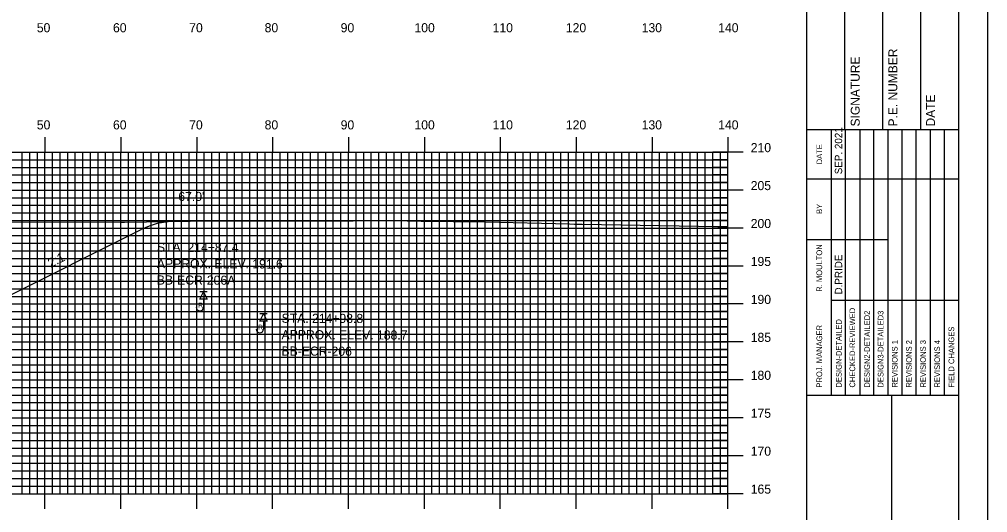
# Model space of a CAD drawing. Extents: x 1796027 to 1796370, y 442591 to 442811.
# Drawn here: x 1796239 to 1796366.6, y 442671.2 to 442736.2 of the extents above; entities that cross this region are included whole.
import ezdxf

# ---------------------------------------------------------------- set-up
doc = ezdxf.new("R2010")
doc.units = 0
for name, color, linetype in [('ANNOTATION', 7, 'Continuous'), ('BORDER', 7, 'Continuous'), ('BORING - REFUSAL', 7, 'Continuous'), ('D_Roadway_Centerline', 7, 'Continuous'), ('D_Text_Standard', 7, 'Continuous'), ('H_V ANNOTATION', 7, 'Continuous'), ('MAJOR', 7, 'Continuous'), ('MINOR', 7, 'Continuous'), ('PLOT BOUNDARY', 7, 'Continuous'), ('S_Roadway_Centerline', 7, 'Continuous')]:
    doc.layers.add(name, color=color, linetype=linetype)

msp = doc.modelspace()

# ---------------------------------------------------------------- linework, layer by layer
at = {"layer": 'ANNOTATION'}
msp.add_line((1796236.65, 442699.27), (1796255.09, 442708.49), dxfattribs=at)
msp.add_arc((1796259.56, 442699.54), 10, 90.854, 116.5651, dxfattribs=at)
at = {"layer": 'BORDER'}
for p, q in [((1796342.79, 442596.67), (1796342.79, 442806.67)), ((1796347.79, 442721.67), (1796347.79, 442738.97)), ((1796352.79, 442721.67), (1796352.79, 442738.97)), ((1796357.79, 442721.67), (1796357.79, 442738.97)), ((1796342.79, 442721.67), (1796362.79, 442721.67)), ((1796342.79, 442686.67), (1796362.79, 442686.67)), ((1796353.97, 442616.67), (1796353.97, 442686.67))]:
    msp.add_line(p, q, dxfattribs=at)
msp.add_lwpolyline([(1796042.79, 442596.67), (1796362.79, 442596.67), (1796362.79, 442806.67), (1796042.79, 442806.67)], close=True, dxfattribs=at)
for points in [[(1796346.02, 442715.17), (1796346.02, 442721.67)], [(1796347.89, 442686.68), (1796347.89, 442721.67)], [(1796349.75, 442721.67), (1796349.75, 442686.68)], [(1796351.61, 442686.68), (1796351.61, 442721.67)], [(1796353.48, 442686.68), (1796353.48, 442721.67)], [(1796355.34, 442686.68), (1796355.34, 442721.67)], [(1796357.2, 442686.68), (1796357.2, 442721.67)], [(1796359.07, 442686.68), (1796359.07, 442721.67)], [(1796360.93, 442686.68), (1796360.93, 442721.67)], [(1796346.02, 442686.68), (1796346.02, 442720.26)], [(1796342.79, 442715.17), (1796362.79, 442715.17)], [(1796342.79, 442707.17), (1796346.02, 442707.17)], [(1796346.02, 442707.17), (1796353.48, 442707.17)], [(1796346.02, 442699.17), (1796362.79, 442699.17)]]:
    msp.add_lwpolyline(points, dxfattribs=at)
at = {"layer": 'BORING - REFUSAL'}
for p, q in [((1796263.77, 442700.27), (1796262.81, 442700.27)), ((1796263.29, 442699.31), (1796263.29, 442698.25)), ((1796271.67, 442697.37), (1796270.71, 442697.37)), ((1796271.19, 442696.41), (1796271.19, 442695.35))]:
    msp.add_line(p, q, dxfattribs=at)
for points in [[(1796263.29, 442700.27), (1796263.77, 442699.31), (1796262.81, 442699.31)], [(1796271.19, 442697.37), (1796271.67, 442696.41), (1796270.71, 442696.41)]]:
    msp.add_lwpolyline(points, close=True, dxfattribs=at)
for centre in [(1796262.81, 442698.25), (1796270.71, 442695.35)]:
    msp.add_arc(centre, 0.485, 180, 0, dxfattribs=at)
at = {"layer": 'D_Roadway_Centerline'}
msp.add_lwpolyline([(1796155.7, 442693.47), (1796158.22, 442683.41), (1796162.22, 442684.41), (1796172.39, 442686.95), (1796180.39, 442687.27), (1796192.39, 442687.03), (1796204.39, 442686.79), (1796212.39, 442686.47), (1796222.57, 442683.93), (1796226.57, 442682.93), (1796230.65, 442699.27), (1796236.65, 442699.27), (1796255.09, 442708.49)], dxfattribs=at)
at = {"layer": 'MAJOR'}
for p, q in [((1796242.39, 442720.67), (1796242.39, 442718.67)), ((1796252.39, 442720.67), (1796252.39, 442718.67)), ((1796262.39, 442720.67), (1796262.39, 442718.67)), ((1796272.39, 442720.67), (1796272.39, 442718.67)), ((1796282.39, 442720.67), (1796282.39, 442718.67)), ((1796292.39, 442720.67), (1796292.39, 442718.67)), ((1796302.39, 442720.67), (1796302.39, 442718.67)), ((1796312.39, 442720.67), (1796312.39, 442718.67)), ((1796322.39, 442720.67), (1796322.39, 442718.67)), ((1796332.39, 442720.67), (1796332.39, 442718.67)), ((1796052.39, 442718.67), (1796332.39, 442718.67)), ((1796052.39, 442718.67), (1796332.39, 442718.67)), ((1796242.39, 442673.67), (1796242.39, 442718.67)), ((1796252.39, 442673.67), (1796252.39, 442718.67)), ((1796262.39, 442673.67), (1796262.39, 442718.67)), ((1796272.39, 442673.67), (1796272.39, 442718.67)), ((1796282.39, 442673.67), (1796282.39, 442718.67)), ((1796292.39, 442673.67), (1796292.39, 442718.67)), ((1796302.39, 442673.67), (1796302.39, 442718.67)), ((1796312.39, 442673.67), (1796312.39, 442718.67)), ((1796322.39, 442673.67), (1796322.39, 442718.67)), ((1796334.4, 442718.67), (1796330.39, 442718.67)), ((1796332.39, 442673.67), (1796332.39, 442718.67)), ((1796332.39, 442673.67), (1796332.39, 442718.67)), ((1796052.39, 442713.67), (1796332.39, 442713.67)), ((1796334.4, 442713.67), (1796330.39, 442713.67)), ((1796052.39, 442708.67), (1796332.39, 442708.67)), ((1796334.4, 442708.67), (1796330.39, 442708.67)), ((1796052.39, 442703.67), (1796332.39, 442703.67)), ((1796334.4, 442703.67), (1796330.39, 442703.67)), ((1796052.39, 442698.67), (1796332.39, 442698.67)), ((1796334.4, 442698.67), (1796330.39, 442698.67)), ((1796052.39, 442693.67), (1796332.39, 442693.67)), ((1796334.4, 442693.67), (1796330.39, 442693.67)), ((1796052.39, 442688.67), (1796332.39, 442688.67)), ((1796334.4, 442688.67), (1796330.39, 442688.67)), ((1796052.39, 442683.67), (1796332.39, 442683.67)), ((1796334.4, 442683.67), (1796330.39, 442683.67)), ((1796052.39, 442678.67), (1796332.39, 442678.67)), ((1796334.4, 442678.67), (1796330.39, 442678.67)), ((1796052.39, 442673.67), (1796332.39, 442673.67)), ((1796052.39, 442673.67), (1796332.39, 442673.67)), ((1796242.39, 442671.66), (1796242.39, 442673.67)), ((1796252.39, 442671.66), (1796252.39, 442673.67)), ((1796262.39, 442671.66), (1796262.39, 442673.67)), ((1796272.39, 442671.66), (1796272.39, 442673.67)), ((1796282.39, 442671.66), (1796282.39, 442673.67)), ((1796292.39, 442671.66), (1796292.39, 442673.67)), ((1796302.39, 442671.66), (1796302.39, 442673.67)), ((1796312.39, 442671.66), (1796312.39, 442673.67)), ((1796322.39, 442671.66), (1796322.39, 442673.67)), ((1796334.4, 442673.67), (1796330.39, 442673.67)), ((1796332.39, 442671.66), (1796332.39, 442673.67))]:
    msp.add_line(p, q, dxfattribs=at)
at = {"layer": 'MINOR'}
for p, q in [((1796239.39, 442673.67), (1796239.39, 442718.67)), ((1796240.39, 442673.67), (1796240.39, 442718.67)), ((1796241.39, 442673.67), (1796241.39, 442718.67)), ((1796243.39, 442673.67), (1796243.39, 442718.67)), ((1796244.39, 442673.67), (1796244.39, 442718.67)), ((1796245.39, 442673.67), (1796245.39, 442718.67)), ((1796246.39, 442673.67), (1796246.39, 442718.67)), ((1796247.39, 442673.67), (1796247.39, 442718.67)), ((1796248.39, 442673.67), (1796248.39, 442718.67)), ((1796249.39, 442673.67), (1796249.39, 442718.67)), ((1796250.39, 442673.67), (1796250.39, 442718.67)), ((1796251.39, 442673.67), (1796251.39, 442718.67)), ((1796253.39, 442673.67), (1796253.39, 442718.67)), ((1796254.39, 442673.67), (1796254.39, 442718.67)), ((1796255.39, 442673.67), (1796255.39, 442718.67)), ((1796256.39, 442673.67), (1796256.39, 442718.67)), ((1796257.39, 442673.67), (1796257.39, 442718.67)), ((1796258.39, 442673.67), (1796258.39, 442718.67)), ((1796259.39, 442673.67), (1796259.39, 442718.67)), ((1796260.39, 442673.67), (1796260.39, 442718.67)), ((1796261.39, 442673.67), (1796261.39, 442718.67)), ((1796263.39, 442673.67), (1796263.39, 442718.67)), ((1796264.39, 442673.67), (1796264.39, 442718.67)), ((1796265.39, 442673.67), (1796265.39, 442718.67)), ((1796266.39, 442673.67), (1796266.39, 442718.67)), ((1796267.39, 442673.67), (1796267.39, 442718.67)), ((1796268.39, 442673.67), (1796268.39, 442718.67)), ((1796269.39, 442673.67), (1796269.39, 442718.67)), ((1796270.39, 442673.67), (1796270.39, 442718.67)), ((1796271.39, 442673.67), (1796271.39, 442718.67)), ((1796273.39, 442673.67), (1796273.39, 442718.67)), ((1796274.39, 442673.67), (1796274.39, 442718.67)), ((1796275.39, 442673.67), (1796275.39, 442718.67)), ((1796276.39, 442673.67), (1796276.39, 442718.67)), ((1796277.39, 442673.67), (1796277.39, 442718.67)), ((1796278.39, 442673.67), (1796278.39, 442718.67)), ((1796279.39, 442673.67), (1796279.39, 442718.67)), ((1796280.39, 442673.67), (1796280.39, 442718.67)), ((1796281.39, 442673.67), (1796281.39, 442718.67)), ((1796283.39, 442673.67), (1796283.39, 442718.67)), ((1796284.39, 442673.67), (1796284.39, 442718.67)), ((1796285.39, 442673.67), (1796285.39, 442718.67)), ((1796286.39, 442673.67), (1796286.39, 442718.67)), ((1796287.39, 442673.67), (1796287.39, 442718.67)), ((1796288.39, 442673.67), (1796288.39, 442718.67)), ((1796289.39, 442673.67), (1796289.39, 442718.67)), ((1796290.39, 442673.67), (1796290.39, 442718.67)), ((1796291.39, 442673.67), (1796291.39, 442718.67)), ((1796293.39, 442673.67), (1796293.39, 442718.67)), ((1796294.39, 442673.67), (1796294.39, 442718.67)), ((1796295.39, 442673.67), (1796295.39, 442718.67)), ((1796296.39, 442673.67), (1796296.39, 442718.67)), ((1796297.39, 442673.67), (1796297.39, 442718.67)), ((1796298.39, 442673.67), (1796298.39, 442718.67)), ((1796299.39, 442673.67), (1796299.39, 442718.67)), ((1796300.39, 442673.67), (1796300.39, 442718.67)), ((1796301.39, 442673.67), (1796301.39, 442718.67)), ((1796303.39, 442673.67), (1796303.39, 442718.67)), ((1796304.39, 442673.67), (1796304.39, 442718.67)), ((1796305.39, 442673.67), (1796305.39, 442718.67)), ((1796306.39, 442673.67), (1796306.39, 442718.67)), ((1796307.39, 442673.67), (1796307.39, 442718.67)), ((1796308.39, 442673.67), (1796308.39, 442718.67)), ((1796309.39, 442673.67), (1796309.39, 442718.67)), ((1796310.39, 442673.67), (1796310.39, 442718.67)), ((1796311.39, 442673.67), (1796311.39, 442718.67)), ((1796313.39, 442673.67), (1796313.39, 442718.67)), ((1796314.39, 442673.67), (1796314.39, 442718.67)), ((1796315.39, 442673.67), (1796315.39, 442718.67)), ((1796316.39, 442673.67), (1796316.39, 442718.67)), ((1796317.39, 442673.67), (1796317.39, 442718.67)), ((1796318.39, 442673.67), (1796318.39, 442718.67)), ((1796319.39, 442673.67), (1796319.39, 442718.67)), ((1796320.39, 442673.67), (1796320.39, 442718.67)), ((1796321.39, 442673.67), (1796321.39, 442718.67)), ((1796323.39, 442673.67), (1796323.39, 442718.67)), ((1796324.39, 442673.67), (1796324.39, 442718.67)), ((1796325.39, 442673.67), (1796325.39, 442718.67)), ((1796326.39, 442673.67), (1796326.39, 442718.67)), ((1796327.39, 442673.67), (1796327.39, 442718.67)), ((1796328.39, 442673.67), (1796328.39, 442718.67)), ((1796329.39, 442673.67), (1796329.39, 442718.67)), ((1796330.39, 442673.67), (1796330.39, 442718.67)), ((1796331.39, 442673.67), (1796331.39, 442718.67)), ((1796052.39, 442717.67), (1796332.39, 442717.67)), ((1796332.39, 442717.67), (1796330.39, 442717.67)), ((1796052.39, 442716.67), (1796332.39, 442716.67)), ((1796052.39, 442715.67), (1796332.39, 442715.67)), ((1796332.39, 442716.67), (1796330.39, 442716.67)), ((1796332.39, 442715.67), (1796330.39, 442715.67)), ((1796052.39, 442714.67), (1796332.39, 442714.67)), ((1796332.39, 442714.67), (1796330.39, 442714.67)), ((1796052.39, 442712.67), (1796332.39, 442712.67)), ((1796332.39, 442712.67), (1796330.39, 442712.67)), ((1796052.39, 442711.67), (1796332.39, 442711.67)), ((1796052.39, 442710.67), (1796332.39, 442710.67)), ((1796332.39, 442711.67), (1796330.39, 442711.67)), ((1796332.39, 442710.67), (1796330.39, 442710.67)), ((1796052.39, 442709.67), (1796332.39, 442709.67)), ((1796332.39, 442709.67), (1796330.39, 442709.67)), ((1796052.39, 442707.67), (1796332.39, 442707.67)), ((1796332.39, 442707.67), (1796330.39, 442707.67)), ((1796052.39, 442706.67), (1796332.39, 442706.67)), ((1796052.39, 442705.67), (1796332.39, 442705.67)), ((1796332.39, 442706.67), (1796330.39, 442706.67)), ((1796332.39, 442705.67), (1796330.39, 442705.67)), ((1796052.39, 442704.67), (1796332.39, 442704.67)), ((1796332.39, 442704.67), (1796330.39, 442704.67)), ((1796052.39, 442702.67), (1796332.39, 442702.67)), ((1796052.39, 442701.67), (1796332.39, 442701.67)), ((1796332.39, 442702.67), (1796330.39, 442702.67)), ((1796332.39, 442701.67), (1796330.39, 442701.67)), ((1796052.39, 442700.67), (1796332.39, 442700.67)), ((1796332.39, 442700.67), (1796330.39, 442700.67)), ((1796052.39, 442699.67), (1796332.39, 442699.67)), ((1796332.39, 442699.67), (1796330.39, 442699.67)), ((1796052.39, 442697.67), (1796332.39, 442697.67)), ((1796052.39, 442696.67), (1796332.39, 442696.67)), ((1796332.39, 442697.67), (1796330.39, 442697.67)), ((1796332.39, 442696.67), (1796330.39, 442696.67)), ((1796052.39, 442695.67), (1796332.39, 442695.67)), ((1796332.39, 442695.67), (1796330.39, 442695.67)), ((1796052.39, 442694.67), (1796332.39, 442694.67)), ((1796332.39, 442694.67), (1796330.39, 442694.67)), ((1796052.39, 442692.67), (1796332.39, 442692.67)), ((1796332.39, 442692.67), (1796330.39, 442692.67)), ((1796052.39, 442691.67), (1796332.39, 442691.67)), ((1796332.39, 442691.67), (1796330.39, 442691.67)), ((1796052.39, 442690.67), (1796332.39, 442690.67)), ((1796332.39, 442690.67), (1796330.39, 442690.67)), ((1796052.39, 442689.67), (1796332.39, 442689.67)), ((1796332.39, 442689.67), (1796330.39, 442689.67)), ((1796052.39, 442687.67), (1796332.39, 442687.67)), ((1796332.39, 442687.67), (1796330.39, 442687.67)), ((1796052.39, 442686.67), (1796332.39, 442686.67)), ((1796332.39, 442686.67), (1796330.39, 442686.67)), ((1796052.39, 442685.67), (1796332.39, 442685.67)), ((1796332.39, 442685.67), (1796330.39, 442685.67)), ((1796052.39, 442684.67), (1796332.39, 442684.67)), ((1796332.39, 442684.67), (1796330.39, 442684.67)), ((1796052.39, 442682.67), (1796332.39, 442682.67)), ((1796332.39, 442682.67), (1796330.39, 442682.67)), ((1796052.39, 442681.67), (1796332.39, 442681.67)), ((1796332.39, 442681.67), (1796330.39, 442681.67)), ((1796052.39, 442680.67), (1796332.39, 442680.67)), ((1796332.39, 442680.67), (1796330.39, 442680.67)), ((1796052.39, 442679.67), (1796332.39, 442679.67)), ((1796332.39, 442679.67), (1796330.39, 442679.67)), ((1796052.39, 442677.67), (1796332.39, 442677.67)), ((1796332.39, 442677.67), (1796330.39, 442677.67)), ((1796052.39, 442676.67), (1796332.39, 442676.67)), ((1796332.39, 442676.67), (1796330.39, 442676.67)), ((1796052.39, 442675.67), (1796332.39, 442675.67)), ((1796332.39, 442675.67), (1796330.39, 442675.67)), ((1796052.39, 442674.67), (1796332.39, 442674.67)), ((1796332.39, 442674.67), (1796330.39, 442674.67))]:
    msp.add_line(p, q, dxfattribs=at)
at = {"layer": 'PLOT BOUNDARY'}
msp.add_lwpolyline([(1796026.61, 442590.55), (1796366.61, 442590.55), (1796366.61, 442810.55), (1796026.61, 442810.55)], close=True, dxfattribs=at)
at = {"layer": 'S_Roadway_Centerline'}
msp.add_lwpolyline([(1796237.54, 442709.5), (1796252.29, 442709.44), (1796252.72, 442709.44), (1796252.77, 442709.44), (1796252.86, 442709.44), (1796264.41, 442709.61), (1796272.07, 442709.64), (1796283.01, 442709.61), (1796288.28, 442709.67), (1796291.96, 442709.59), (1796300.38, 442709.48), (1796311.5, 442709.21), (1796312.18, 442709.2), (1796313.19, 442709.18), (1796331.05, 442708.89), (1796332.39, 442708.89)], dxfattribs=at)

# ---------------------------------------------------------------- texts
at = {"layer": 'ANNOTATION'}
msp.add_text('2:1', height=1.2, rotation=26.5651, dxfattribs=at).set_placement((1796243.14, 442703.42))
at = {"layer": 'BORDER'}
for s, height, p in [('P.E. NUMBER', 1.1811, (1796354.71, 442722.06)), ('SIGNATURE', 1.181, (1796349.75, 442722.06)), ('DATE', 1.181, (1796359.67, 442722.06)), ('SEP. 2021', 0.969, (1796347.44, 442715.76)), ('DATE', 0.743, (1796344.8, 442717.08)), ('BY', 0.743, (1796344.8, 442710.54)), ('R. MOULTON', 0.745, (1796344.8, 442700.28)), ('D.PRIDE', 0.969, (1796347.44, 442699.92)), ('CHECKED-REVIEWED', 0.7455, (1796349.15, 442687.65)), ('DESIGN-DETAILED', 0.7455, (1796347.37, 442687.65)), ('DESIGN2-DETAILED2', 0.7455, (1796351.09, 442687.65)), ('DESIGN3-DETAILED3', 0.7455, (1796352.88, 442687.65)), ('PROJ. MANAGER', 0.7455, (1796344.8, 442687.65)), ('FIELD CHANGES', 0.7455, (1796362.2, 442687.65)), ('REVISIONS 1', 0.7455, (1796354.74, 442687.65)), ('REVISIONS 2', 0.7455, (1796356.61, 442687.65)), ('REVISIONS 3', 0.7455, (1796358.47, 442687.65)), ('REVISIONS 4', 0.7455, (1796360.33, 442687.65))]:
    msp.add_text(s, height=height, rotation=90, dxfattribs=at).set_placement(p)
at = {"layer": 'BORING - REFUSAL'}
for s, p in [('STA. 214+87.4', (1796257.15, 442705.55)), ('APPROX. ELEV. 191.6', (1796257.14, 442703.39)), ('BB-ECR-206A', (1796257.13, 442701.23)), ('STA. 214+98.8', (1796273.57, 442696.19)), ('APPROX. ELEV. 188.7', (1796273.57, 442694.03)), ('BB-ECR-206', (1796273.56, 442691.87))]:
    msp.add_text(s, height=1.2, rotation=359.8142, dxfattribs=at).set_placement(p)
for p in [(1796262.58, 442698.19), (1796270.48, 442695.29)]:
    msp.add_text('R', height=0.64, dxfattribs=at).set_placement(p)
at = {"layer": 'D_Text_Standard'}
msp.add_text("67.0'", height=1.2, dxfattribs=at).set_placement((1796259.97, 442712.24))
at = {"layer": 'H_V ANNOTATION'}
for s, p in [('50', (1796241.32, 442734.47)), ('60', (1796251.36, 442734.47)), ('70', (1796261.4, 442734.47)), ('80', (1796271.34, 442734.47)), ('90', (1796281.36, 442734.47)), ('100', (1796291.08, 442734.47)), ('110', (1796301.38, 442734.47)), ('120', (1796311.03, 442734.47)), ('130', (1796321.02, 442734.47)), ('140', (1796331.1, 442734.47)), ('50', (1796241.32, 442721.67)), ('60', (1796251.36, 442721.67)), ('70', (1796261.4, 442721.67)), ('80', (1796271.34, 442721.67)), ('90', (1796281.36, 442721.67)), ('100', (1796291.08, 442721.67)), ('110', (1796301.38, 442721.67)), ('120', (1796311.03, 442721.67)), ('130', (1796321.02, 442721.67)), ('140', (1796331.1, 442721.67)), ('210', (1796335.39, 442718.67)), ('205', (1796335.39, 442713.67)), ('200', (1796335.39, 442708.67)), ('195', (1796335.39, 442703.67)), ('190', (1796335.39, 442698.67)), ('185', (1796335.39, 442693.67)), ('180', (1796335.39, 442688.67)), ('175', (1796335.39, 442683.67)), ('170', (1796335.39, 442678.67)), ('165', (1796335.39, 442673.67))]:
    msp.add_text(s, height=1.2, dxfattribs=at).set_placement(p)

doc.saveas('drawing.dxf')
